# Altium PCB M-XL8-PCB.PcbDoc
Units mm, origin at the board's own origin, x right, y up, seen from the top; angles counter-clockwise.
Board outline 15 x 14.8 mm, 4 copper layers (Top Layer, GND, POWER, Bottom Layer), stack 0.778 mm thick; 11 components, 28 nets, 32 pads, 0 vias.
Unrouted connection lines stored in the file: 57.
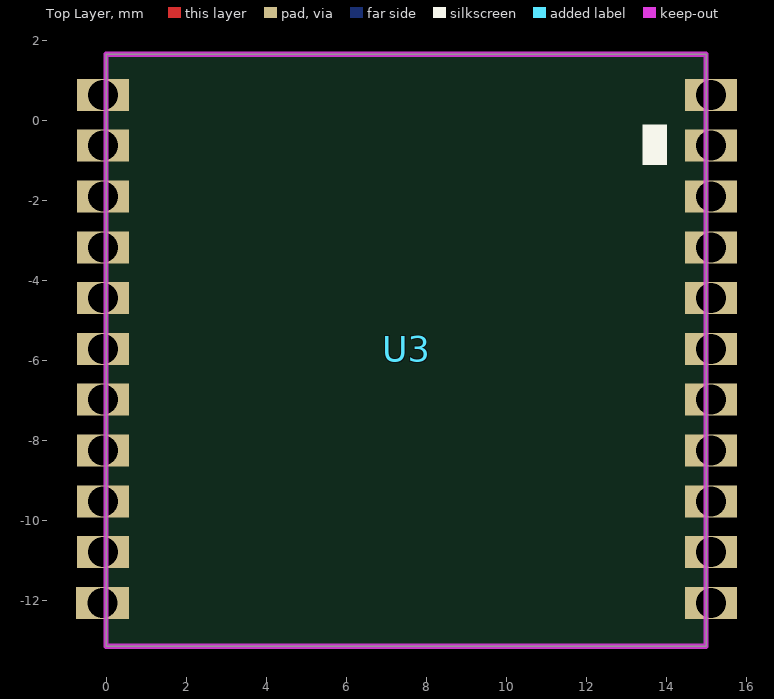
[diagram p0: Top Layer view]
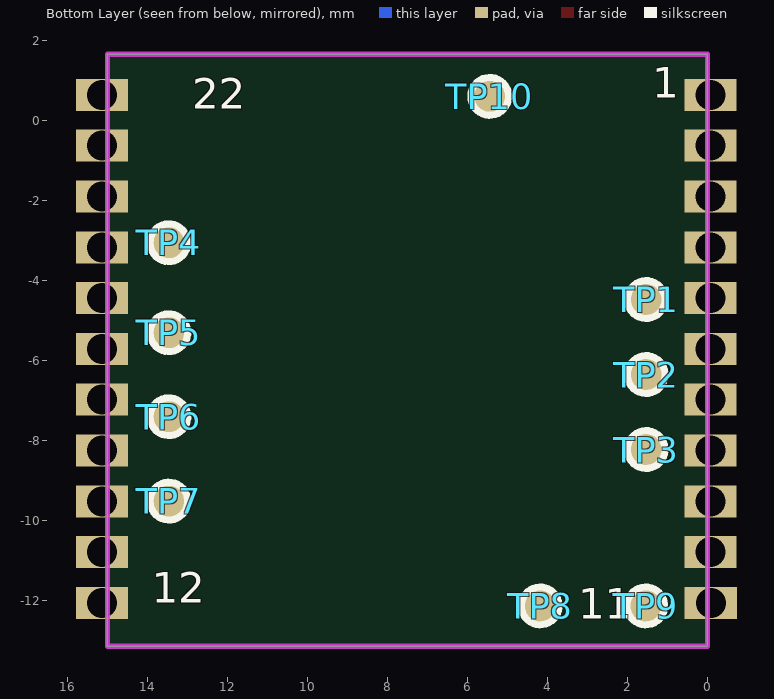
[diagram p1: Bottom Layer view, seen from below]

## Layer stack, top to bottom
Top Solder: solder mask 0.0102, Solder Resist, Dk 3.5
Top Layer: signal copper 0.0356
Dielectric 1: core 0.254, FR-4, Dk 4.2
GND: signal copper 0.036
Dielectric 3: prepreg 0.127, Dk 4.2
POWER: signal copper 0.036
Dielectric 2: core 0.254, Dk 4.2
Bottom Layer: signal copper 0.0356
Bottom Solder: solder mask 0.0102, Solder Resist, Dk 3.5

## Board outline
0,-13.147 0,1.653 15,1.653 15,-13.147

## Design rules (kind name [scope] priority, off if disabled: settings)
Clearance Clearance_50 [InNetClass('50R')] p1: gap=0.1 ignorepadtopadclearanceinfootprint=FALSE except(0: Arc-Hole Track-Hole SMDPad-Hole THPad-Hole Via-Hole Fill-Hole Poly-Hole Region-Hole Text-Hole)
Clearance [All] p2: gap=0.1 ignorepadtopadclearanceinfootprint=FALSE except(0: Arc-Hole Track-Hole SMDPad-Hole THPad-Hole Via-Hole Fill-Hole Poly-Hole Region-Hole Text-Hole)
ComponentClearance [All] p1 off: gap=0.025 collisioncheckmode=3 verticalgap=0.025 showdistances=FALSE
HoleToHoleClearance [All] p1: gap=0.127 allowstackedmicrovias=TRUE
MinimumSolderMaskSliver [All] p1: minsoldermaskwidth=0.102
PasteMaskExpansion [All] p1: expansion=0.051
PlaneClearance [All] p1: clearance=0.127
PlaneConnect [All] p1: planeconnectstyle=Direct reliefexpansion=0.508 reliefentries=2 reliefconductorwidth=0.254 reliefairgap=0.254
PolygonConnect [All] p1: connectstyle=Direct reliefconductorwidth=0.254 reliefentries=2 polygonreliefangle="90 Angle" airgapwidth=0.254
RoutingCorners [All] p1: cornerstyle=45-Degree minsetback=1.27 maxsetback=2.54
RoutingVias [All] p1: holewidth=0.25 width=0.5 viastyle="Through Hole" minholewidth=0.25 minwidth=0.5 maxholewidth=0.25 maxwidth=0.5
SilkToSilkClearance [All] p1: silktosilkclearance=0.127
SilkToSolderMaskClearance [IsPad] p1: minsilkscreentomaskgap=0.127 clearancetoexposedcopper=TRUE
SolderMaskExpansion [All] p1: expansion=0.1
Width Width_50R [InNetClass('50R')] p1: maxlimit=0.165 minlimit=0.165 preferedwidth=0.165
Width [All] p2: maxlimit=2.54 minlimit=0.1 preferedwidth=0.254
21 further rules are at their usual default settings.

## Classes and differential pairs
net class 50R: ANT NetC6_1 NetC6_2 NetC7_2 NetC12_1 NetC12_2 NetC15_1 NetC19_2 NetL2_1

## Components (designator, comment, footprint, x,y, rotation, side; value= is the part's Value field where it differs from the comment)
TP1 "Test-Point" TP08A 1.53,-4.48 r90 bottom
TP2 "Test-Point" TP08A 1.53,-6.355 r90 bottom
TP3 "Test-Point" TP08A 1.53,-8.23 r90 bottom
TP4 "Test-Point" TP08A 13.462,-3.06 r90 bottom
TP5 "Test-Point" TP08A 13.462,-5.31 r90 bottom
TP6 "Test-Point" TP08A 13.462,-7.409 r90 bottom
TP7 "Test-Point" TP08A 13.462,-9.52 r90 bottom
TP8 "Test-Point" TP08A 4.18,-12.14 r90 bottom
TP9 "Test-Point" TP08A 1.54,-12.14 r90 bottom
TP10 "Test-Point" TP08A 5.44,0.6 r90 bottom
U3 "M-XL78" M-XL78 7.5,-5.747 r0 top locked

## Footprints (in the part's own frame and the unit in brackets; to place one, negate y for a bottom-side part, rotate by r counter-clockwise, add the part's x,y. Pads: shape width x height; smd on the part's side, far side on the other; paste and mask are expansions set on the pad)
M-XL78 [mm]
  rect 1.3x0.8 hole 0.75 paste-0.5: 1(-7.577,6.382) 2(-7.577,5.112) 3(-7.577,3.842) 4(-7.577,2.572) 5(-7.577,1.302) 6(-7.577,0.032) 7(-7.577,-1.238) 8(-7.577,-2.508) 9(-7.577,-3.778) 10(-7.577,-5.048) 12(7.627,-6.318) 13(7.627,-5.048) 14(7.627,-3.778) 15(7.627,-2.508) 16(7.627,-1.238) 17(7.627,0.032) 18(7.627,1.302) 19(7.627,2.572) 20(7.627,3.842) 21(7.627,5.112) 22(7.627,6.382)
  rect 1.321x0.8 hole 0.75 paste-0.5: 11(-7.587,-6.318)
  Keep-Out Layer lines w0.127: -7.5,-7.4 -7.5,7.4 7.5,7.4 7.5,-7.4 -7.5,-7.4
TP08A [mm]
  round 0.9 smd: 1(0,0)
  silkscreen extent -0.47,-0.47 0.47,0.47

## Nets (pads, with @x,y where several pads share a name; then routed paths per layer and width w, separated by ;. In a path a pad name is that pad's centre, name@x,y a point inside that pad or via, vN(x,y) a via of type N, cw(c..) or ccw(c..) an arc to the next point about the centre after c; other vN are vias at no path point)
ANT: U3.21
D3.3V: TP9.1 U3.13
GND: TP10.1 U3.1 U3.2 U3.3 U3.4 U3.11 U3.12 U3.19 U3.20 U3.22
MISO: TP7.1 U3.15
MOSI: TP6.1 U3.16
NetC1_2: 
NetC2_2: 
NetC6_1: 
NetC6_2: 
NetC7_2: 
NetC9_1: 
NetC10_2: 
NetC12_1: 
NetC12_2: 
NetC15_1: 
NetC19_2: 
NetC20_1: 
NetL2_1: 
NSS: TP5.1 U3.17
"RF RXTX": 
RF_DIO0: TP1.1 U3.5
RF_DIO1: TP2.1 U3.6
RF_DIO2: U3.7
RF_DIO3: TP3.1 U3.8
RF_DIO4: U3.9
RF_DIO5: U3.10
RF_NRESET: TP4.1 U3.18
SCK: TP8.1 U3.14

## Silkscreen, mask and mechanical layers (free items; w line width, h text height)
Top Overlay:
  rectangle: 13.411,-1.118 14.021,-0.102
Bottom Overlay:
  text "1" at 1.372,0.559 h0.76
  text "22" at 12.88,0.29 h0.76
  text "12" at 13.894,-12.065 h0.76
  text "11" at 3.23,-12.46 h0.76
Top Paste:
  lines w0.6: 13.716,-1.245 13.716,-12.649 1.277,-12.649 1.277,1.245 13.723,1.245 13.716,-0.051
Top Solder:
  lines w0.6: 13.723,-1.245 13.723,-12.649 1.277,-12.649 1.277,1.245 13.723,1.245 13.723,-0.051
Bottom Solder:
  lines w0.45: 14.71,-0.94 cw(c14.71,-0.64) 14.71,-0.34
  lines w0.8: 14.8,-1.91 cw(c14.8,-0.64) 14.8,0.63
